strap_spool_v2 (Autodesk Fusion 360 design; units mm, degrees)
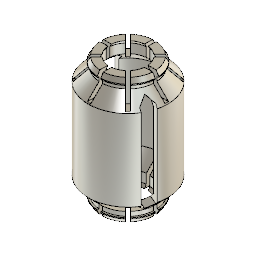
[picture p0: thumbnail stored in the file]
sketch "Skizze1" plane through (0, 0, 0) normal (0, 1, 0) x axis (1, 0, 0)
  dimension "d1" = 120
  dimension "d2" = 0.3
  dimension "d3" = 135
  dimension "d4" = 5
  dimension "d5" = 7.5
  dimension "d6" = 0.2
  dimension "d7" = 0.5
  dimension "d8" = 1.2
  dimension "d9" = 15
revolve "Drehen" sketch "Skizze1" AlongAngle 360 bodies "Spulenkorper"
sketch "Skizze2" plane through (0, 0, 0) normal (0, 0, -1) x axis (1, 0, 0)
  dimension "d13" = 0.5
  dimension "d14" = 0.5
  dimension "d16" = 360
shell "Schale" innerThickness 2
extrude "Extrusion1" cut sketch "Skizze2" against normal blind 6
sketch "Skizze3" plane through (0, 0, 17.7124) normal (0, 0, 1) x axis (-1, 0, 0)
  dimension "d20" = 30
  dimension "d21" = 3.5
extrude "Extrusion2" new body sketch "Skizze3" against normal blind 14
move "Verschieben1" RotateAngle 22.5
chamfer "Fase" distance 1.75
combine "Kombinieren1"
copy_paste_bodies "Körper kopieren/einfügen"
move "Verschieben2"
move "Verschieben3"
move "Verschieben4" RotateAngle -45
combine "Kombinieren2"
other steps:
base_feature "Basiselement"
named bodies: "Spulenkorper"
